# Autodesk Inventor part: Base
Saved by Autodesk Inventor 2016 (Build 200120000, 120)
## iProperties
Created: 2017-06
Part Number: Base
Material: Generic
Document SubType Name: Modeling
Designer: Administrator
Appearance: Generic
Author: Administrator
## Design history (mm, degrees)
feature "Body1"
body "Solid1"
